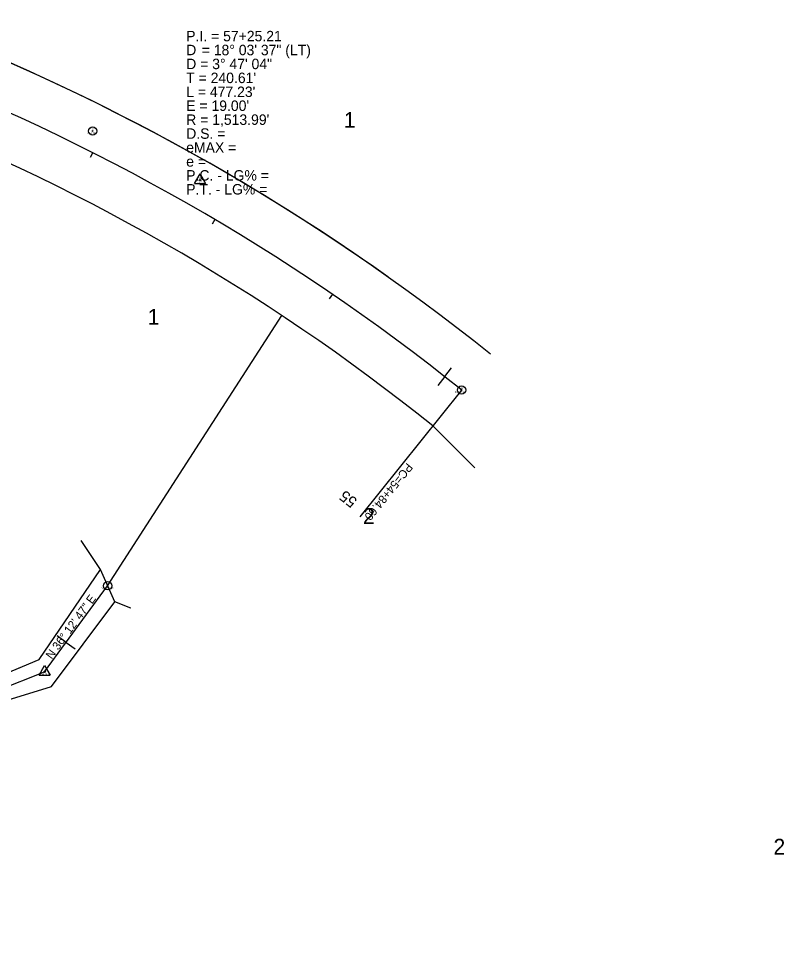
# Model space of a CAD drawing. Extents: x 2519952 to 2531965, y 848341 to 887632.
# Drawn here: x 2531312 to 2531861, y 852515 to 853191 of the extents above; entities that cross this region are included whole.
import ezdxf

# ---------------------------------------------------------------- set-up
doc = ezdxf.new("R2010")
doc.units = 0
for name, color, linetype in [('RD_EX_DV_Prop', 7, 'Continuous'), ('RD_EX_DV_TX_Prop', 7, 'Continuous'), ('RD_EX_H2O', 7, 'Continuous'), ('RD_EX_Misc', 7, 'Continuous'), ('RD_EX_RW', 7, 'Continuous'), ('RD_HC_Cl', 7, 'Continuous'), ('RD_HC_Data', 7, 'Continuous'), ('RD_HC_Data_Tic', 7, 'Continuous'), ('RD_HC_Survey_txCode', 7, 'Continuous'), ('RD_HC_TX_Sta50', 7, 'Continuous'), ('RD_HC_txCode', 7, 'Continuous'), ('RD_SMD_Locator', 7, 'Continuous')]:
    doc.layers.add(name, color=color, linetype=linetype)

msp = doc.modelspace()

# ---------------------------------------------------------------- linework, layer by layer
at = {"layer": 'RD_EX_DV_Prop'}
for p, q in [((2531375.38, 852784.26), (2531500.43, 852978.19)), ((2531608.7, 852899.09), (2531638.89, 852868.83)), ((2531330.16, 852722.5), (2531375.38, 852784.26)), ((2531217.01, 852678.01), (2531330.16, 852722.5))]:
    msp.add_line(p, q, dxfattribs=at)
for radius, start, end in [(1546.99, 54.66603, 69.31315), (1480.99, 51.25287, 69.31316)]:
    msp.add_arc((2530681.77, 851744.04), radius, start, end, dxfattribs=at)
at = {"layer": 'RD_EX_H2O'}
for points in [[(2531213.69, 852682.74), (2531217.87, 852686.11), (2531234.1, 852691.83), (2531269.14, 852707.42), (2531326.15, 852731.33), (2531370.16, 852795.85)], [(2531026, 852501), (2531071.02, 852545.11), (2531039.2, 852568.21), (2531031.58, 852587.1), (2531073.27, 852639.92), (2531117.65, 852680.26), (2531161.62, 852675.64), (2531189.82, 852659.94), (2531218.15, 852670.26), (2531220.29, 852673.34), (2531239, 852678.46), (2531271.99, 852692.49), (2531334.99, 852711.84), (2531380.55, 852772.77)]]:
    msp.add_lwpolyline(points, dxfattribs=at)
at = {"layer": 'RD_EX_Misc'}
msp.add_lwpolyline([(2531392.13, 852768.21), (2531380.55, 852772.77), (2531370.16, 852795.85), (2531356.42, 852816.73)], dxfattribs=at)
at = {"layer": 'RD_EX_RW'}
for radius in [1546.99, 1480.99]:
    msp.add_arc((2530681.77, 851744.04), radius, 51.25288, 69.31313, dxfattribs=at)
at = {"layer": 'RD_HC_Cl'}
for p, q in [((2531330.16, 852722.5), (2531375.38, 852784.26)), ((2531217.01, 852678.01), (2531330.16, 852722.5))]:
    msp.add_line(p, q, dxfattribs=at)
msp.add_arc((2530681.77, 851744.04), 1513.99, 51.25288, 69.31313, dxfattribs=at)
at = {"layer": 'RD_HC_Data'}
for p, q in [((2531437.73, 853073.12), (2531441.7, 853080)), ((2531441.7, 853080), (2531445.67, 853073.12)), ((2531437.73, 853073.12), (2531445.67, 853073.12)), ((2531629.35, 852924.82), (2531556.32, 852833.81)), ((2531326.19, 852720.2), (2531330.16, 852727.08)), ((2531330.16, 852727.08), (2531334.13, 852720.2)), ((2531326.19, 852720.2), (2531334.13, 852720.2))]:
    msp.add_line(p, q, dxfattribs=at)
for centre, radius in [((2531364.63, 853110.76), 3), ((2531364.63, 853110.76), 0.282), ((2531441.7, 853075.42), 0.529), ((2531629.35, 852924.82), 3), ((2531629.35, 852924.82), 0.282), ((2531375.38, 852784.26), 3), ((2531375.38, 852784.26), 0.282), ((2531330.16, 852722.5), 0.529)]:
    msp.add_circle(centre, radius, dxfattribs=at)
at = {"layer": 'RD_HC_Data_Tic'}
for p, q in [((2531364.65, 853095.27), (2531362.85, 853091.7)), ((2531452.35, 853047.25), (2531450.31, 853043.81)), ((2531536.68, 852993.55), (2531534.43, 852990.25)), ((2531617.29, 852934.4), (2531622.24, 852940.69)), ((2531617.29, 852934.4), (2531612.35, 852928.11)), ((2531345.64, 852743.65), (2531339.19, 852748.38)), ((2531345.64, 852743.65), (2531352.1, 852738.92))]:
    msp.add_line(p, q, dxfattribs=at)
at = {"layer": 'RD_SMD_Locator'}
for centre in [(2531364.63, 853110.76), (2531441.7, 853075.42), (2531629.35, 852924.82), (2531356.42, 852816.73), (2531370.16, 852795.85), (2531370.16, 852795.85), (2531375.38, 852784.26), (2531380.55, 852772.77), (2531380.55, 852772.77), (2531392.13, 852768.21), (2531326.15, 852731.33), (2531330.16, 852722.5), (2531334.99, 852711.84)]:
    msp.add_circle(centre, 0.001, dxfattribs=at)

# ---------------------------------------------------------------- texts
at = {"layer": 'RD_EX_DV_TX_Prop'}
for s, p in [('1', (2531544.89, 853113.05)), ('1', (2531404.19, 852971.75)), ('2', (2531558.57, 852828.61)), ('2', (2531853.17, 852591.29))]:
    msp.add_text(s, height=11.32, dxfattribs=at).set_placement(p)
at = {"layer": 'RD_HC_Data'}
for s, rotation, p in [('PC=54+84.60', 231.25288, (2531590.23, 852872.88)), ('N 36%%d 12\' 47" E', 53.78702, (2531335.25, 852731.14))]:
    msp.add_text(s, height=6, rotation=rotation, dxfattribs=at).set_placement(p)
at = {"layer": 'RD_HC_Survey_txCode'}
for s, p in [('P.I. = 57+25.21', (2531431.76, 853175.17)), ('    = 18%%d 03\' 37" (LT)', (2531431.76, 853165.17)), ('D', (2531431.76, 853165.17)), ('D = 3%%d 47\' 04"', (2531431.76, 853155.17)), ("T = 240.61'", (2531431.76, 853145.17)), ("L = 477.23'", (2531431.76, 853135.17)), ("E = 19.00'", (2531431.76, 853125.17)), ("R = 1,513.99'", (2531431.76, 853115.17)), ('D.S. = ', (2531431.76, 853105.17)), ('eMAX = ', (2531431.76, 853095.17)), ('e = ', (2531431.76, 853085.17)), ('P.C. - LG% = ', (2531431.76, 853075.17)), ('P.T. - LG% = ', (2531431.76, 853065.17))]:
    msp.add_text(s, height=7.5, dxfattribs=at).set_placement(p)
at = {"layer": 'RD_HC_TX_Sta50'}
msp.add_text('55', height=8, rotation=141.83568, dxfattribs=at).set_placement((2531555.09, 852845.93))
at = {"layer": 'RD_HC_txCode'}
for s, p in [('9', (2531364.35, 853111.76)), ('CP 9 MSC', (2531361, 853108.76)), ('PI 57+21.22', (2531437.92, 853073.42)), ('22', (2531440.96, 853076.42)), ('PC 54+84.60', (2531624.61, 852922.82)), ('21', (2531628.9, 852925.82)), ('POT 15+50.33', (2531370.43, 852782.26)), ('43', (2531374.65, 852785.26)), ('PI 14+73.78', (2531326.38, 852720.5)), ('42', (2531329.42, 852723.5))]:
    msp.add_text(s, height=1, dxfattribs=at).set_placement(p)

doc.saveas('drawing.dxf')
